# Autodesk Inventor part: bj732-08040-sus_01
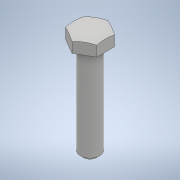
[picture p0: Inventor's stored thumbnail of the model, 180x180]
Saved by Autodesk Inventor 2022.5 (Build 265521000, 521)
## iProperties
Part Number: bj732-08040-sus_01
Material: 一般
Document SubType Name: Modeling
Designer: ImaoCorp
Density: 1 g/cm^3
Appearance: 既定
Author: ImaoCorp
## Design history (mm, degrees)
feature "bj732-08040-sus_01"
node "ソリッド1"
